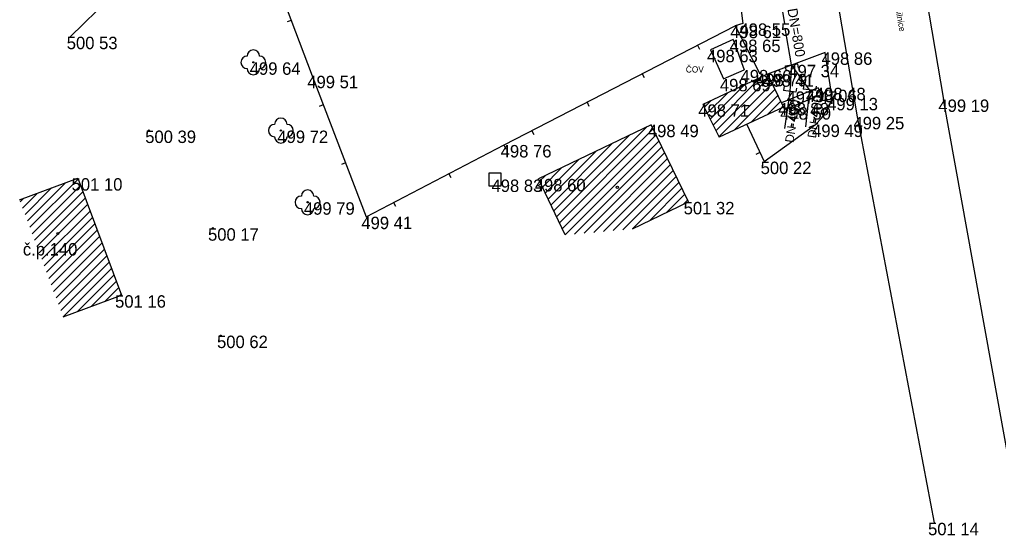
# Model space of a CAD drawing. Extents: x -554123 to -553118, y -1076825 to -1073672.
# Drawn here: x -553505.6 to -553426.8, y -1076809.5 to -1076768 of the extents above; entities that cross this region are included whole.
import ezdxf

# ---------------------------------------------------------------- set-up
doc = ezdxf.new("R2010")
doc.units = 0
for name, color, linetype in [('1', 7, 'Continuous'), ('12', 7, 'Continuous'), ('14', 7, 'Continuous'), ('17', 7, 'Continuous'), ('18', 7, 'Continuous'), ('27', 7, 'Continuous'), ('28', 7, 'Continuous'), ('32', 7, 'Continuous'), ('34', 7, 'Continuous'), ('40', 7, 'Continuous'), ('47', 7, 'Continuous'), ('49', 7, 'Continuous'), ('50', 7, 'Continuous'), ('52', 7, 'Continuous'), ('54', 7, 'Continuous'), ('6', 7, 'Continuous')]:
    doc.layers.add(name, color=color, linetype=linetype)

# ---------------------------------------------------------------- blocks, each defined once
blk = doc.blocks.new('POINT_DISPLAY')
blk.add_line((0, 0), (0, 0))
blk = doc.blocks.new('JS800')
at = {"layer": '49'}
blk.add_text('DN=800', height=0.8, rotation=359.99988, dxfattribs=at).set_placement((0, 0))
blk = doc.blocks.new('JS400')
at = {"layer": '49'}
for p, q in [((1.852, 0.799), (1.853, 0)), ((1.1, 0.435), (1.346, 0.434)), ((1.101, 0.303), (1.346, 0.303))]:
    blk.add_line(p, q, dxfattribs=at)
for points in [[(1.852, 0.799), (1.569, 0.265), (1.999, 0.265)], [(2.358, 0.8), (2.273, 0.763), (2.215, 0.642), (2.187, 0.454), (2.188, 0.34), (2.216, 0.151), (2.272, 0.038), (2.357, -0.001), (2.415, 0), (2.5, 0.038), (2.56, 0.151), (2.589, 0.341), (2.588, 0.453), (2.561, 0.642), (2.5, 0.763), (2.414, 0.8), (2.358, 0.8)], [(2.952, 0.8), (2.868, 0.762), (2.81, 0.643), (2.783, 0.454), (2.782, 0.34), (2.811, 0.152), (2.868, 0.038), (2.952, 0), (3.009, 0), (3.094, 0.038), (3.156, 0.152), (3.183, 0.341), (3.184, 0.454), (3.155, 0.643), (3.094, 0.763), (3.01, 0.799), (2.952, 0.8)]]:
    blk.add_lwpolyline(points, dxfattribs=at)
blk.add_text('DN', height=0.7, dxfattribs=at).set_placement((-0.2, 0.074))
blk = doc.blocks.new('SA')
at = {"layer": '50'}
blk.add_lwpolyline([(-0.5, -0.5), (0.5, -0.5), (0.5, 0.5), (-0.5, 0.5)], close=True, dxfattribs=at)
blk = doc.blocks.new('T')
at = {"layer": '6'}
blk.add_circle((0, 0), 0.05, dxfattribs=at)
blk = doc.blocks.new('STL')
at = {"layer": '34'}
blk.add_circle((0, 0), 0.05, dxfattribs=at)
for centre, start, end in [((0, 0.5), 0, 180), ((-0.5, 0), 90, 270), ((0.5, 0), 270, 90), ((0, -0.5), 180, 0)]:
    blk.add_arc(centre, 0.5, start, end, dxfattribs=at)
blk = doc.blocks.new('VYUST')
at = {"layer": '40'}
for p, q in [((-0.35, 0.501), (0, 0.5)), ((0, 0.5), (0, -0.5)), ((0, 0), (3, 0)), ((-0.35, -0.5), (0, -0.5))]:
    blk.add_line(p, q, dxfattribs=at)
blk = doc.blocks.new('BN')
at = {"layer": '47'}
blk.add_line((-0.25, 0), (0.25, 0), dxfattribs=at)
blk = doc.blocks.new('BZ')
at = {"layer": '47'}
blk.add_circle((0, 0), 0.0875, dxfattribs=at)

msp = doc.modelspace()

# ---------------------------------------------------------------- linework, layer by layer
at = {"layer": '12'}
for p, q in [((-553450.54, -1076744.62), (-553447.37, -1076768.32)), ((-553501.52, -1076769.39), (-553488.17, -1076756.39)), ((-553488.17, -1076756.39), (-553482.04, -1076772.53)), ((-553483.732, -1076768.076), (-553484.059, -1076768.2)), ((-553466.58, -1076778.1), (-553447.99, -1076768.5)), ((-553447.37, -1076768.32), (-553447.99, -1076768.5)), ((-553447.99, -1076768.5), (-553446.01, -1076772.37)), ((-553451.031, -1076770.07), (-553450.87, -1076770.381)), ((-553455.473, -1076772.365), (-553455.313, -1076772.676)), ((-553482.04, -1076772.53), (-553477.7, -1076783.87)), ((-553459.916, -1076774.659), (-553459.756, -1076774.97)), ((-553481.146, -1076774.865), (-553481.473, -1076774.99)), ((-553464.359, -1076776.953), (-553464.198, -1076777.264)), ((-553447.056, -1076776.44), (-553445.66, -1076779.44)), ((-553477.7, -1076783.87), (-553466.58, -1076778.1)), ((-553466.605, -1076778.113), (-553466.444, -1076778.423)), ((-553446.001, -1076778.707), (-553446.319, -1076778.854)), ((-553479.359, -1076779.535), (-553479.686, -1076779.66)), ((-553471.043, -1076780.416), (-553470.882, -1076780.726)), ((-553475.481, -1076782.719), (-553475.32, -1076783.029))]:
    msp.add_line(p, q, dxfattribs=at)
at = {"layer": '14'}
for p, q in [((-553445.38, -1076772.41), (-553450.58, -1076774.83)), ((-553445.38, -1076772.41), (-553444.09, -1076775.06)), ((-553450.58, -1076774.83), (-553449.29, -1076777.48)), ((-553444.09, -1076775.06), (-553449.29, -1076777.48)), ((-553454.74, -1076776.47), (-553463.83, -1076780.83)), ((-553451.75, -1076782.68), (-553454.74, -1076776.47)), ((-553505.595, -1076782.516), (-553500.91, -1076780.77)), ((-553500.91, -1076780.77), (-553497.4, -1076790.19)), ((-553461.668, -1076785.338), (-553463.83, -1076780.83)), ((-553456.255, -1076784.849), (-553451.75, -1076782.68)), ((-553502.085, -1076791.936), (-553497.4, -1076790.19))]:
    msp.add_line(p, q, dxfattribs=at)
at = {"layer": '17'}
for p, q in [((-553441.16, -1076758.15), (-553438.18, -1076775.84)), ((-553434.09, -1076757.5), (-553431.22, -1076774.44)), ((-553425.47, -1076806.18), (-553431.22, -1076774.44)), ((-553438.18, -1076775.84), (-553431.98, -1076808.5))]:
    msp.add_line(p, q, dxfattribs=at)
at = {"layer": '18'}
for p, q in [((-553448.14, -1076769.62), (-553449.97, -1076770.44)), ((-553448.14, -1076769.62), (-553447.26, -1076772.06)), ((-553449.97, -1076770.44), (-553448.92, -1076772.78)), ((-553448.92, -1076772.78), (-553447.26, -1076772.06)), ((-553441.31, -1076773.5), (-553444.26, -1076774.72)), ((-553441.31, -1076773.5), (-553441.08, -1076774.054)), ((-553441.08, -1076774.054), (-553444.03, -1076775.274)), ((-553444.09, -1076775.06), (-553444.03, -1076775.274))]:
    msp.add_line(p, q, dxfattribs=at)
at = {"layer": '27'}
for p, q in [((-553440.75, -1076770.65), (-553445.38, -1076772.41)), ((-553440.19, -1076774.31), (-553440.75, -1076770.65)), ((-553445.66, -1076779.44), (-553441.51, -1076776.46))]:
    msp.add_line(p, q, dxfattribs=at)
msp.add_lwpolyline([(-553441.51, -1076776.46), (-553441.013, -1076775.928), (-553440.682, -1076775.423), (-553440.368, -1076774.865), (-553440.19, -1076774.31)], dxfattribs=at)
at = {"layer": '28'}
for p, q in [((-553443.45, -1076771.65), (-553443.6, -1076773.79)), ((-553442.01, -1076773.65), (-553443.45, -1076771.65))]:
    msp.add_line(p, q, dxfattribs=at)
at = {"layer": '32'}
for p, q in [((-553449.769, -1076776.496), (-553445.946, -1076772.673)), ((-553449.537, -1076776.972), (-553445.248, -1076772.682)), ((-553449.306, -1076777.447), (-553445.016, -1076773.158)), ((-553450.232, -1076775.545), (-553448.591, -1076773.905)), ((-553450, -1076776.021), (-553447.269, -1076773.289)), ((-553448.058, -1076776.907), (-553444.785, -1076773.633)), ((-553450.463, -1076775.069), (-553449.914, -1076774.52)), ((-553446.735, -1076776.291), (-553444.553, -1076774.109)), ((-553445.413, -1076775.676), (-553444.322, -1076774.584)), ((-553462.364, -1076783.887), (-553455.138, -1076776.661)), ((-553462.135, -1076784.365), (-553454.577, -1076776.808)), ((-553462.822, -1076782.931), (-553457.856, -1076777.964)), ((-553462.593, -1076783.409), (-553456.497, -1076777.313)), ((-553461.906, -1076784.843), (-553454.348, -1076777.285)), ((-553461.676, -1076785.321), (-553454.118, -1076777.762)), ((-553463.052, -1076782.453), (-553459.215, -1076778.616)), ((-553460.919, -1076785.27), (-553453.888, -1076778.239)), ((-553460.142, -1076785.2), (-553453.658, -1076778.717)), ((-553463.281, -1076781.975), (-553460.574, -1076779.268)), ((-553459.364, -1076785.13), (-553453.428, -1076779.194)), ((-553463.51, -1076781.497), (-553461.932, -1076779.92)), ((-553458.587, -1076785.06), (-553453.199, -1076779.671)), ((-553457.81, -1076784.989), (-553452.969, -1076780.149)), ((-553504.772, -1076784.724), (-553500.885, -1076780.837)), ((-553463.739, -1076781.019), (-553463.291, -1076780.572)), ((-553457.032, -1076784.919), (-553452.739, -1076780.626)), ((-553456.255, -1076784.849), (-553452.509, -1076781.103)), ((-553505.156, -1076783.694), (-553503.019, -1076781.556)), ((-553504.964, -1076784.209), (-553501.891, -1076781.136)), ((-553504.58, -1076785.239), (-553500.693, -1076781.352)), ((-553504.388, -1076785.754), (-553500.501, -1076781.867)), ((-553454.891, -1076784.192), (-553452.279, -1076781.58)), ((-553505.54, -1076782.663), (-553505.273, -1076782.396)), ((-553505.348, -1076783.178), (-553504.146, -1076781.976)), ((-553504.196, -1076786.269), (-553500.309, -1076782.382)), ((-553453.528, -1076783.536), (-553452.05, -1076782.058)), ((-553452.164, -1076782.879), (-553451.82, -1076782.535)), ((-553504.005, -1076786.784), (-553500.117, -1076782.897)), ((-553503.813, -1076787.3), (-553499.925, -1076783.412)), ((-553503.621, -1076787.815), (-553499.733, -1076783.928)), ((-553503.429, -1076788.33), (-553499.541, -1076784.443)), ((-553503.237, -1076788.845), (-553499.35, -1076784.958)), ((-553503.045, -1076789.36), (-553499.158, -1076785.473)), ((-553502.853, -1076789.875), (-553498.966, -1076785.988)), ((-553502.661, -1076790.391), (-553498.774, -1076786.503)), ((-553502.469, -1076790.906), (-553498.582, -1076787.019)), ((-553502.277, -1076791.421), (-553498.39, -1076787.534)), ((-553502.085, -1076791.936), (-553498.198, -1076788.049)), ((-553500.958, -1076791.516), (-553498.006, -1076788.564)), ((-553499.831, -1076791.096), (-553497.814, -1076789.079)), ((-553498.703, -1076790.676), (-553497.622, -1076789.594)), ((-553497.576, -1076790.256), (-553497.43, -1076790.109))]:
    msp.add_line(p, q, dxfattribs=at)

# ---------------------------------------------------------------- block references
at = {"layer": '1'}
for p in [(-553447.99, -1076768.5), (-553447.37, -1076768.32), (-553501.52, -1076769.39), (-553448.14, -1076769.62), (-553449.97, -1076770.44), (-553440.75, -1076770.65), (-553486.78, -1076771.45), (-553443.45, -1076771.65), (-553443.45, -1076771.65), (-553447.26, -1076772.06), (-553446.01, -1076772.37), (-553445.38, -1076772.41), (-553482.04, -1076772.53), (-553448.92, -1076772.78), (-553443.6, -1076773.79), (-553443.6, -1076773.79), (-553442.01, -1076773.65), (-553441.31, -1076773.5), (-553444.26, -1076774.72), (-553440.19, -1076774.31), (-553431.22, -1076774.44), (-553450.58, -1076774.83), (-553444.09, -1076775.06), (-553438.18, -1076775.84), (-553495.19, -1076776.94), (-553484.56, -1076776.94), (-553454.74, -1076776.47), (-553441.51, -1076776.46), (-553466.58, -1076778.1), (-553445.66, -1076779.44), (-553500.91, -1076780.77), (-553467.33, -1076780.88), (-553463.83, -1076780.83), (-553451.75, -1076782.68), (-553482.41, -1076782.71), (-553477.7, -1076783.87), (-553490.04, -1076784.8), (-553497.4, -1076790.19), (-553489.41, -1076793.44), (-553431.98, -1076808.5)]:
    msp.add_blockref('POINT_DISPLAY', p, dxfattribs=at)
at = {"layer": '32'}
for p in [(-553456.255, -1076784.849), (-553502.085, -1076791.936)]:
    msp.add_blockref('POINT_DISPLAY', p, dxfattribs=at)
at = {"layer": '34'}
for p in [(-553486.78, -1076771.45), (-553484.56, -1076776.94), (-553482.41, -1076782.71)]:
    msp.add_blockref('STL', p, dxfattribs=at)
at = {"layer": '40'}
for p, xscale, yscale, rotation in [((-553444.51, -1076765.39), 1.000000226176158, 1.000000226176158, -80.38924721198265), ((-553443.45, -1076771.65), 1.000000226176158, 1.000000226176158, 99.61075278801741), ((-553443.6, -1076773.79), 0.9999995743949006, 0.9999995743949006, -98.1198770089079), ((-553442.01, -1076773.65), 1.0000003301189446, 1.0000003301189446, -96.09033926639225)]:
    msp.add_blockref('VYUST', p, dxfattribs=dict(at, xscale=xscale, yscale=yscale, rotation=rotation))
at = {"layer": '47'}
for name, p in [('BN', (-553447.104, -1076774.911)), ('BZ', (-553457.473, -1076781.509)), ('BZ', (-553502.515, -1076785.219))]:
    msp.add_blockref(name, p, dxfattribs=at)
at = {"layer": '49'}
for name, p, xscale, yscale, rotation in [('JS800', (-553443.788, -1076767.17), 0.9999985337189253, 0.9999985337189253, -80.2438855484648), ('JS400', (-553443.187, -1076777.765), 0.9999974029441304, 0.9999974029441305, 81.63531725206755), ('JS400', (-553441.384, -1076777.395), 0.9999974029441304, 0.9999974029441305, 81.63531725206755)]:
    msp.add_blockref(name, p, dxfattribs=dict(at, xscale=xscale, yscale=yscale, rotation=rotation))
at = {"layer": '50'}
msp.add_blockref('SA', (-553467.33, -1076780.88), dxfattribs=at)
at = {"layer": '6'}
for p in [(-553495.19, -1076776.94), (-553490.04, -1076784.8), (-553489.41, -1076793.44)]:
    msp.add_blockref('T', p, dxfattribs=at)

# ---------------------------------------------------------------- texts
at = {"layer": '52'}
msp.add_text('asf.silnice', height=0.5, rotation=280.74882, dxfattribs=at).set_placement((-553435.297, -1076766.121))
msp.add_text('ČOV', height=0.5, dxfattribs=at).set_placement((-553451.961, -1076772.269))
at = {"layer": '54'}
msp.add_text('č.p.140', height=1, dxfattribs=at).set_placement((-553505.331, -1076786.992))
at = {"layer": '6'}
for s, p in [('498 61 ', (-553448.383, -1076769.5)), ('498 55 ', (-553447.644, -1076769.32)), ('500 53 ', (-553501.798, -1076770.39)), ('498 65 ', (-553448.426, -1076770.62)), ('498 63 ', (-553450.256, -1076771.44)), ('498 86 ', (-553441.036, -1076771.65)), ('499 64 ', (-553487.066, -1076772.45)), ('497 34 ', (-553443.71, -1076772.65)), ('497 34 ', (-553443.71, -1076772.65)), ('498 66 ', (-553447.558, -1076773.06)), ('498 79 ', (-553446.294, -1076773.37)), ('498 41 ', (-553445.749, -1076773.41)), ('499 51 ', (-553482.433, -1076773.53)), ('498 69 ', (-553449.218, -1076773.78)), ('497 47 ', (-553443.858, -1076774.79)), ('497 47 ', (-553443.858, -1076774.79)), ('498 06 ', (-553442.298, -1076774.65)), ('498 48 ', (-553441.572, -1076774.5)), ('498 71 ', (-553450.959, -1076775.83)), ('498 48 ', (-553444.522, -1076775.72)), ('499 13 ', (-553440.585, -1076775.31)), ('499 19 ', (-553431.627, -1076775.44)), ('498 50 ', (-553444.366, -1076776.06)), ('499 25 ', (-553438.466, -1076776.84)), ('500 39 ', (-553495.48, -1076777.94)), ('499 72 ', (-553484.844, -1076777.94)), ('498 49 ', (-553455.014, -1076777.47)), ('499 49 ', (-553441.796, -1076777.46)), ('498 76 ', (-553466.864, -1076779.1)), ('500 22 ', (-553445.938, -1076780.44)), ('501 10 ', (-553501.406, -1076781.77)), ('498 83 ', (-553467.604, -1076781.88)), ('498 60 ', (-553464.118, -1076781.83)), ('499 79 ', (-553482.706, -1076783.71)), ('501 32 ', (-553452.135, -1076783.68)), ('499 41 ', (-553478.081, -1076784.87)), ('500 17 ', (-553490.425, -1076785.8)), ('501 16 ', (-553497.906, -1076791.19)), ('500 62 ', (-553489.7, -1076794.44)), ('501 14 ', (-553432.462, -1076809.5))]:
    msp.add_text(s, height=1, dxfattribs=at).set_placement(p)

doc.saveas('drawing.dxf')
